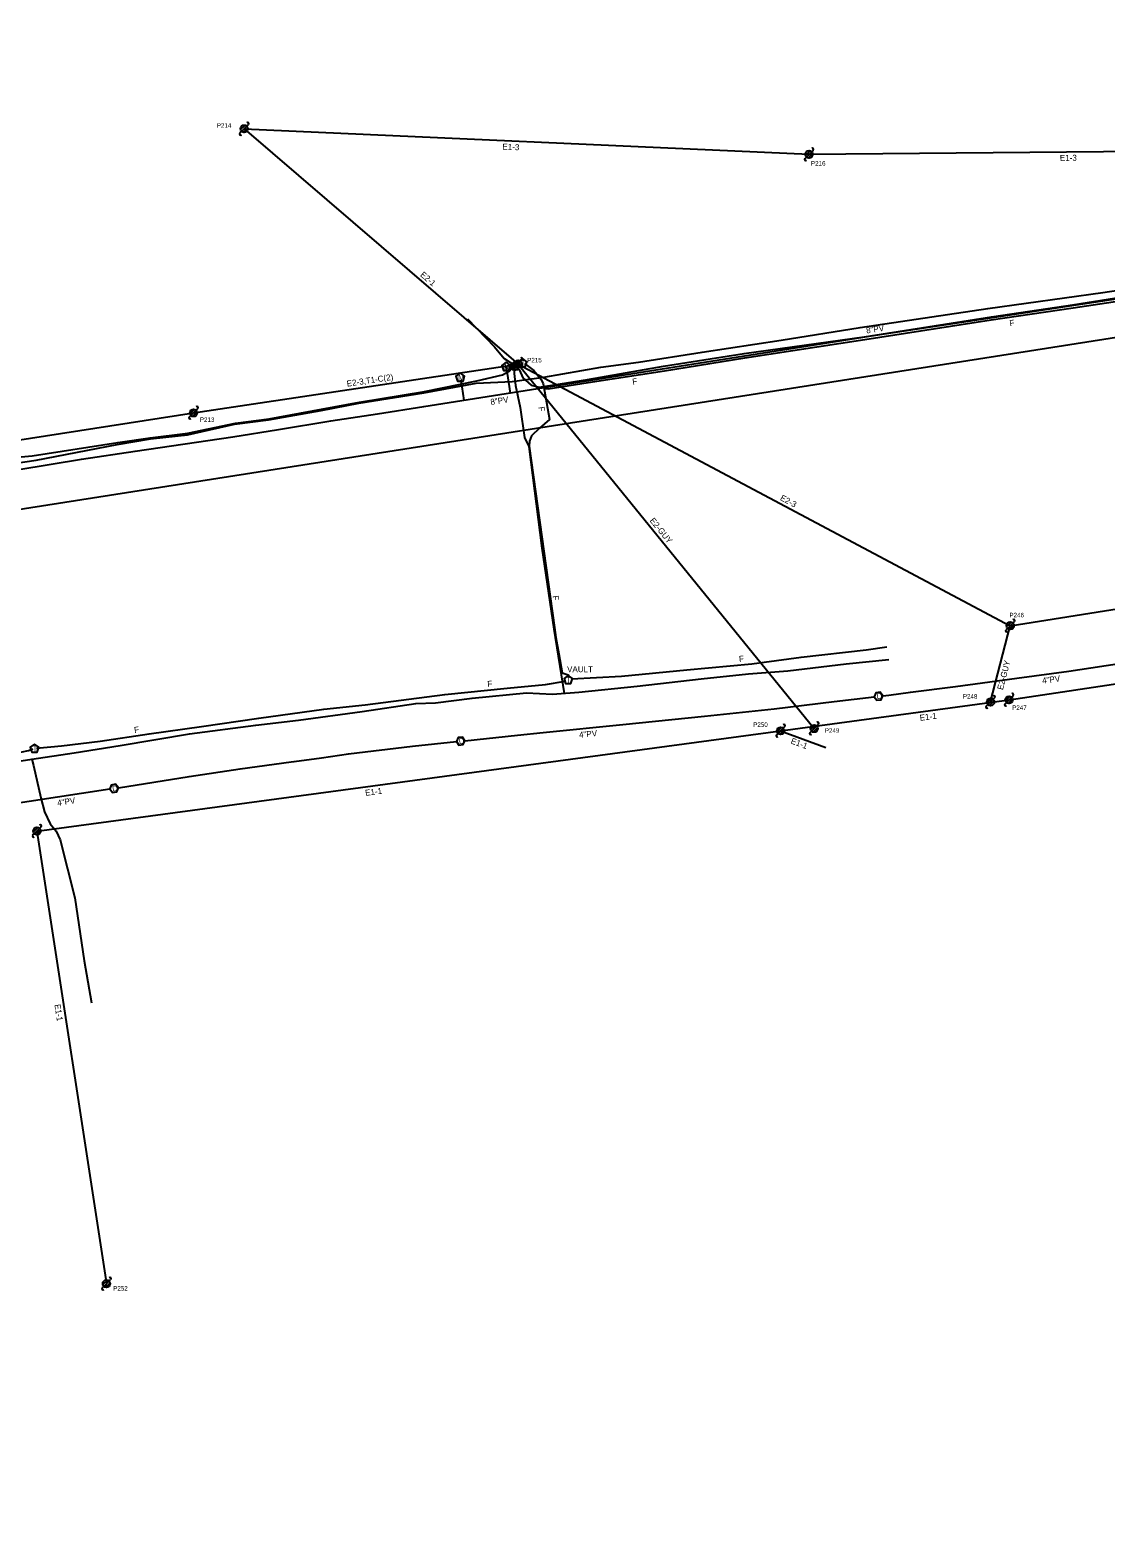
# Model space of a CAD drawing. Extents: x 1614474 to 1865144, y 1098877 to 1212550.
# Drawn here: x 1775065 to 1775781, y 1179234 to 1180237 of the extents above; entities that cross this region are included whole.
import ezdxf

# ---------------------------------------------------------------- set-up
doc = ezdxf.new("R2010")
doc.units = 0
for name, color, linetype in [('BFUSER_FIBERSPAN', 7, 'Continuous'), ('RD_EX_SU_H2O', 7, 'Continuous'), ('RD_EX_SU_Ovhd', 7, 'Continuous'), ('RD_EX_SU_Pole', 7, 'Continuous'), ('RD_EX_SU_Telecom', 7, 'Continuous'), ('RD_EX_SU_TX_H2O', 7, 'Continuous'), ('RD_EX_SU_TX_Pole', 7, 'Continuous'), ('RD_EX_SU_TX_Telecom', 7, 'Continuous')]:
    doc.layers.add(name, color=color, linetype=linetype)

# ---------------------------------------------------------------- blocks, each defined once
blk = doc.blocks.new('SUE_PP')
at = {"layer": 'RD_EX_SU_Pole'}
for p, q in [((-2.4, -0.6), (0.6, 2.4)), ((-1.8, -1.8), (1.8, 1.8)), ((-0.6, -2.4), (2.4, 0.6)), ((1.8, 1.8), (2.8, 2.8)), ((-2.8, -2.8), (-1.8, -1.8))]:
    blk.add_line(p, q, dxfattribs=at)
blk.add_circle((0, 0), 2.5, dxfattribs=at)
for centre, start, end in [((2.3, 3.4), 315, 135), ((-2.3, -3.4), 135, 315)]:
    blk.add_arc(centre, 0.75, start, end, dxfattribs=at)
blk = doc.blocks.new('SUE_TPP')
at = {"layer": 'RD_EX_SU_Telecom'}
blk.add_lwpolyline([(0, 3), (-2.9, 0.9), (-1.8, -2.4), (1.8, -2.4), (2.9, 0.9)], close=True, dxfattribs=at)
blk.add_text('T', height=3.75, dxfattribs=at).set_placement((-1.3, -1.9))
blk = doc.blocks.new('SUE_WM')
at = {"layer": 'RD_EX_SU_H2O'}
blk.add_lwpolyline([(0, 3.1), (-2.9, 0.9), (-1.8, -2.5), (1.8, -2.5), (2.9, 0.9)], close=True, dxfattribs=at)
blk.add_text('M', height=3.75, dxfattribs=at).set_placement((-1.4, -1.9))

msp = doc.modelspace()

# ---------------------------------------------------------------- linework, layer by layer
at = {"layer": 'BFUSER_FIBERSPAN'}
msp.add_lwpolyline([(1772266.1, 1179233.7), (1772993.3, 1179552.4), (1773074.8, 1179562.2), (1773346.2, 1179631.6), (1773610.7, 1179692.1), (1774668.7, 1179856.8), (1776115.7, 1180083.9)], dxfattribs=at)
at = {"layer": 'RD_EX_SU_H2O'}
for p, q in [((1775381.9, 1180012.8), (1775384.6, 1179995.3)), ((1775351.7, 1180003.9), (1775353.8, 1179990.5))]:
    msp.add_line(p, q, dxfattribs=at)
for points in [[(1775079.3, 1179947.9), (1775099.6, 1179951.3), (1775135.1, 1179956.7), (1775200.1, 1179966.2), (1775230.5, 1179971.1), (1775265.3, 1179976.8), (1775296.4, 1179981.4), (1775327.1, 1179986.3), (1775627.5, 1180033.7), (1775910.5, 1180076.5), (1776287.1, 1180136.1), (1776361.3, 1180146.7), (1776578.8, 1180172.8), (1776784.6, 1180199.9), (1777026.8, 1180236.7)], [(1774386.6, 1179840.7), (1774523.7, 1179861.6), (1774695.3, 1179888.5), (1774728, 1179893.4), (1774787.8, 1179902.9), (1774821.8, 1179908.7), (1774868.7, 1179916), (1774901.1, 1179921), (1774935.6, 1179926), (1774973, 1179931.3), (1775005.5, 1179936.4), (1775033.5, 1179940.5), (1775079.3, 1179947.9)], [(1775632.4, 1179793.9), (1775636.3, 1179794.4), (1775650.8, 1179796.3), (1775680.6, 1179800.1), (1775721.5, 1179805.6), (1775756.1, 1179810.3), (1775795.6, 1179816.3), (1775846, 1179823.9)], [(1775354.5, 1179764), (1775389.5, 1179767.7), (1775406.4, 1179769.5), (1775459.4, 1179774.8), (1775513.9, 1179780.3), (1775560.1, 1179785.3), (1775600, 1179790), (1775626.6, 1179793.2)], [(1775124, 1179732.7), (1775171.2, 1179740.1), (1775205.1, 1179745.2), (1775239, 1179749.9), (1775241, 1179750.2), (1775259.1, 1179752.7), (1775277.1, 1179755.2), (1775319.6, 1179760.3), (1775348.8, 1179763.4)], [(1774863.9, 1179692.3), (1774894.8, 1179697.6), (1774947.5, 1179706.1), (1774977.8, 1179710.7), (1775010.9, 1179715.6), (1775118.3, 1179731.9)], [(1775124, 1179732.7), (1775124, 1179732.7)]]:
    msp.add_lwpolyline(points, dxfattribs=at)
for points in [[(1775632.4, 1179793.9), (1775630.6, 1179796.2), (1775627.8, 1179795.9), (1775626.6, 1179793.2), (1775628.4, 1179790.9), (1775631.2, 1179791.3)], [(1775354.5, 1179764), (1775352.8, 1179766.4), (1775350, 1179766.1), (1775348.8, 1179763.4), (1775350.5, 1179761.1), (1775353.4, 1179761.4)], [(1775124, 1179732.7), (1775122.2, 1179735), (1775119.3, 1179734.5), (1775118.3, 1179731.9), (1775120.1, 1179729.6), (1775122.9, 1179730)]]:
    msp.add_lwpolyline(points, close=True, dxfattribs=at)
at = {"layer": 'RD_EX_SU_Ovhd'}
for p, q in [((1775207.7, 1180171.1), (1775389.8, 1180014.6)), ((1775207.7, 1180171.1), (1775583.3, 1180154.1)), ((1775583.3, 1180154.1), (1775904.1, 1180157.1)), ((1775174, 1179982.1), (1775389.8, 1180014.6)), ((1775389.8, 1180014.6), (1775717.1, 1179840.5)), ((1775389.8, 1180014.6), (1775586.7, 1179772.1)), ((1774915.7, 1179942), (1775174, 1179982.1)), ((1775717.1, 1179840.5), (1775883.7, 1179867)), ((1775704, 1179789.8), (1775717.1, 1179840.5)), ((1775716.3, 1179791.2), (1775985, 1179831.9)), ((1775564.4, 1179770.6), (1775716.3, 1179791.2)), ((1775069.9, 1179703.9), (1775564.4, 1179770.6)), ((1775564.4, 1179770.6), (1775594.5, 1179759.4)), ((1775069.9, 1179703.9), (1775116.1, 1179402.8))]:
    msp.add_line(p, q, dxfattribs=at)
at = {"layer": 'RD_EX_SU_Pole'}
for p, q in [((1775585.1, 1180155.8), (1775586.2, 1180156.9)), ((1775580.5, 1180151.2), (1775581.6, 1180152.3)), ((1775580.9, 1180153.4), (1775584, 1180156.5)), ((1775581.6, 1180152.3), (1775585.1, 1180155.8)), ((1775582.7, 1180151.6), (1775585.7, 1180154.7)), ((1775387.4, 1180013.9), (1775390.4, 1180017)), ((1775388, 1180012.8), (1775391.5, 1180016.4)), ((1775391.5, 1180016.4), (1775392.6, 1180017.4)), ((1775387, 1180011.8), (1775388, 1180012.8)), ((1775389.1, 1180012.2), (1775392.2, 1180015.2)), ((1775171.1, 1179979.3), (1775172.2, 1179980.4)), ((1775171.6, 1179981.5), (1775174.6, 1179984.6)), ((1775172.2, 1179980.4), (1775175.7, 1179983.9)), ((1775173.3, 1179979.7), (1775176.4, 1179982.8)), ((1775175.7, 1179983.9), (1775176.8, 1179985)), ((1775714.3, 1179837.7), (1775715.4, 1179838.7)), ((1775714.7, 1179839.9), (1775717.8, 1179842.9)), ((1775715.4, 1179838.7), (1775718.9, 1179842.3)), ((1775716.5, 1179838.1), (1775719.5, 1179841.1)), ((1775718.9, 1179842.3), (1775720, 1179843.3)), ((1775701.2, 1179787), (1775702.2, 1179788.1)), ((1775701.6, 1179789.2), (1775704.6, 1179792.3)), ((1775702.2, 1179788.1), (1775705.7, 1179791.6)), ((1775703.3, 1179787.4), (1775706.4, 1179790.5)), ((1775705.7, 1179791.6), (1775706.8, 1179792.7)), ((1775713.5, 1179788.4), (1775714.6, 1179789.5)), ((1775713.9, 1179790.6), (1775717, 1179793.7)), ((1775714.6, 1179789.5), (1775718.1, 1179793)), ((1775715.7, 1179788.8), (1775718.8, 1179791.9)), ((1775718.1, 1179793), (1775719.2, 1179794.1)), ((1775561.6, 1179767.8), (1775562.7, 1179768.9)), ((1775562, 1179770), (1775565.1, 1179773)), ((1775562.7, 1179768.9), (1775566.2, 1179772.4)), ((1775563.8, 1179768.2), (1775566.9, 1179771.3)), ((1775566.2, 1179772.4), (1775567.3, 1179773.5)), ((1775583.9, 1179769.3), (1775585, 1179770.4)), ((1775584.3, 1179771.5), (1775587.4, 1179774.5)), ((1775585, 1179770.4), (1775588.5, 1179773.9)), ((1775586.1, 1179769.7), (1775589.1, 1179772.8)), ((1775588.5, 1179773.9), (1775589.6, 1179775)), ((1775067.5, 1179703.3), (1775070.5, 1179706.3)), ((1775068.1, 1179702.1), (1775071.6, 1179705.7)), ((1775071.6, 1179705.7), (1775072.7, 1179706.7)), ((1775067, 1179701.1), (1775068.1, 1179702.1)), ((1775069.2, 1179701.5), (1775072.3, 1179704.6))]:
    msp.add_line(p, q, dxfattribs=at)
for centre in [(1775583.3, 1180154.1), (1775389.8, 1180014.6), (1775174, 1179982.1), (1775717.1, 1179840.5), (1775704, 1179789.8), (1775716.3, 1179791.2), (1775564.4, 1179770.6), (1775586.7, 1179772.1), (1775069.9, 1179703.9)]:
    msp.add_circle(centre, 2.5, dxfattribs=at)
for centre, start, end in [((1775585.6, 1180157.4), 315, 135), ((1775581, 1180150.7), 135, 315), ((1775392.1, 1180018), 315, 135), ((1775387.5, 1180011.2), 135, 315), ((1775176.3, 1179985.5), 315, 135), ((1775171.7, 1179978.8), 135, 315), ((1775714.8, 1179837.1), 135, 315), ((1775719.4, 1179843.9), 315, 135), ((1775701.7, 1179786.5), 135, 315), ((1775706.3, 1179793.2), 315, 135), ((1775714, 1179787.9), 135, 315), ((1775718.6, 1179794.6), 315, 135), ((1775589, 1179775.5), 315, 135), ((1775562.1, 1179767.3), 135, 315), ((1775566.7, 1179774), 315, 135), ((1775584.4, 1179768.8), 135, 315), ((1775072.2, 1179707.3), 315, 135), ((1775067.6, 1179700.5), 135, 315)]:
    msp.add_arc(centre, 0.75, start, end, dxfattribs=at)
at = {"layer": 'RD_EX_SU_Telecom'}
for points in [[(1775037.7, 1179945.9), (1775069.3, 1179950.6), (1775123.2, 1179961.1), (1775145.4, 1179964.9), (1775169.9, 1179967.6), (1775201.2, 1179974.6), (1775223.9, 1179977.5), (1775258.9, 1179983.7), (1775284, 1179988.6), (1775327.2, 1179995.4), (1775361.9, 1180001.9), (1775385.8, 1180002.9), (1775406.9, 1180005.8), (1775444.8, 1180012.4), (1775469.8, 1180015.8), (1775512.2, 1180022.4), (1775564.7, 1180030.5), (1775617.4, 1180039), (1775702.3, 1180051.6), (1775778.6, 1180062.1), (1775845.7, 1180072.1)], [(1775388, 1180012.7), (1775390.8, 1180010.6), (1775392.9, 1180005.4), (1775398.5, 1180000.6), (1775403.9, 1179999.3), (1775436, 1180004.3), (1775486.6, 1180013.1), (1775540.2, 1180021.6), (1775620, 1180032.7), (1775704.6, 1180045.9), (1775758.4, 1180054), (1775815.8, 1180063)], [(1775407.1, 1179998.4), (1775409.8, 1179998), (1775436.5, 1180002.4), (1775487.1, 1180010.1), (1775540.6, 1180018.8), (1775620.3, 1180031), (1775704.5, 1180044), (1775758.9, 1180052), (1775816.5, 1180060.6)], [(1775356.1, 1180044.6), (1775374.1, 1180026), (1775380.6, 1180018.3), (1775387.4, 1180013.8)], [(1774916.4, 1179941), (1774920.4, 1179939.4), (1774950.3, 1179943.9), (1774992, 1179946.4), (1775014.9, 1179949.3), (1775047.5, 1179951.7), (1775066.7, 1179953.5), (1775123.7, 1179962.4), (1775145.1, 1179965.6), (1775170.3, 1179968.6), (1775201.9, 1179975.3), (1775224.4, 1179978.2), (1775259, 1179984.5), (1775284.4, 1179989.3), (1775327.6, 1179996.4), (1775362.3, 1180003.4), (1775379.4, 1180007.4), (1775383.8, 1180009.8), (1775387.1, 1180013.3)], [(1775387.5, 1180012.6), (1775387.2, 1180008.4), (1775388.1, 1180000.4), (1775391.2, 1179985.6), (1775394.1, 1179965.8), (1775396.9, 1179959.8)], [(1775394.1, 1180014.9), (1775400.2, 1180010.2), (1775405.1, 1180004.3), (1775406.4, 1180001.5), (1775407.5, 1179996.6), (1775410.8, 1179977.8), (1775404, 1179971.9), (1775398.8, 1179966.8), (1775397.5, 1179963.3), (1775397.2, 1179959.9), (1775414.1, 1179839.3), (1775415, 1179832.6), (1775417, 1179821.7), (1775419.1, 1179809.2), (1775423.2, 1179807.9), (1775423.8, 1179805.9)], [(1775396.9, 1179959.8), (1775405.6, 1179892.2), (1775413.7, 1179838.3), (1775420.5, 1179795.5)], [(1775425.3, 1179805.1), (1775458.6, 1179806.9), (1775502, 1179811.1), (1775545.3, 1179815.2), (1775578.1, 1179819.6), (1775621.3, 1179824.5), (1775635.1, 1179826.4)], [(1775066.5, 1179751.8), (1775094.7, 1179756), (1775125.3, 1179760.9), (1775171.3, 1179768.5), (1775215.5, 1179774.3), (1775243.7, 1179777.6), (1775286.1, 1179783.5), (1775321.8, 1179788.7), (1775334.9, 1179789.3), (1775359.4, 1179792.4), (1775395.4, 1179795.9), (1775412.7, 1179794.9), (1775430.3, 1179796.2), (1775469.1, 1179800.4), (1775511.6, 1179805.2), (1775543, 1179808.6), (1775569.3, 1179810.4), (1775608, 1179815.1), (1775636.3, 1179818.1)], [(1775069.5, 1179759), (1775086.1, 1179760.6), (1775112, 1179763.6), (1775144.6, 1179768.6), (1775179.4, 1179773.5), (1775217.4, 1179779), (1775260.7, 1179785.1), (1775288.2, 1179787.9), (1775341.2, 1179794.7), (1775382.5, 1179799), (1775408, 1179801.5), (1775421.2, 1179803.6)], [(1774491.4, 1179669.3), (1774493.5, 1179668), (1774512.2, 1179669.4), (1774555.8, 1179675.6), (1774603.4, 1179682.2), (1774648.2, 1179689.7), (1774702.1, 1179698.6), (1774733, 1179702.8), (1774777, 1179710.9), (1774837.9, 1179722.2), (1774863.8, 1179726), (1774901.6, 1179732.2), (1774961.5, 1179741.6), (1775003.6, 1179748.2), (1775055.9, 1179755.8), (1775064.3, 1179757.6), (1775067.1, 1179758.6)], [(1775042.1, 1179747.9), (1775066.5, 1179751.8), (1775067.6, 1179747.6), (1775072.5, 1179726.1), (1775075, 1179716.7), (1775078.6, 1179708.7), (1775082.6, 1179703.8), (1775085.4, 1179698.1), (1775095, 1179659.6), (1775101.2, 1179617.6), (1775106.1, 1179589.7)]]:
    msp.add_lwpolyline(points, dxfattribs=at)
for points in [[(1775392.8, 1180018.2), (1775390, 1180016.1), (1775391, 1180012.8), (1775394.6, 1180012.8), (1775395.7, 1180016.1)], [(1775423.2, 1179807.5), (1775420.4, 1179805.4), (1775421.4, 1179802), (1775425, 1179802), (1775426.1, 1179805.4)], [(1775068.3, 1179761.8), (1775065.4, 1179759.7), (1775066.5, 1179756.4), (1775070, 1179756.4), (1775071.1, 1179759.7)]]:
    msp.add_lwpolyline(points, close=True, dxfattribs=at)

# ---------------------------------------------------------------- block references
at = {"layer": 'RD_EX_SU_H2O'}
for p in [(1775351.4, 1180005.6), (1775381.9, 1180012.8)]:
    msp.add_blockref('SUE_WM', p, dxfattribs=at)
at = {"layer": 'RD_EX_SU_Pole'}
for p in [(1775207.7, 1180171.1), (1775116.1, 1179402.8)]:
    msp.add_blockref('SUE_PP', p, dxfattribs=at)
at = {"layer": 'RD_EX_SU_Telecom'}
msp.add_blockref('SUE_TPP', (1775387.8, 1180013.4), dxfattribs=at)

# ---------------------------------------------------------------- texts
at = {"layer": 'RD_EX_SU_H2O'}
for rotation, p in [(6.9094, (1775628.5, 1179791.6)), (6.0433, (1775350.6, 1179761.7)), (8.6121, (1775120.2, 1179730.2))]:
    msp.add_text('D', height=3.75, rotation=rotation, dxfattribs=at).set_placement(p)
at = {"layer": 'RD_EX_SU_Ovhd'}
for s, rotation, p in [('E1-3', 357.3993, (1775379.3, 1180157.3)), ('E1-3', 0.5501, (1775750.1, 1180149.7)), ('E2-1', 319.3118, (1775324.4, 1180073.4)), ('E2-3,T1-C(2)', 8.5529, (1775276.2, 1179999.5)), ('E2-3', 331.9941, (1775563.7, 1179924.3)), ('E2-GUY', 309.0861, (1775477.1, 1179910.3)), ('E2-GUY', 75.4571, (1775712.2, 1179797.5)), ('E1-1', 7.7281, (1775657.2, 1179777.2)), ('E1-1', 339.5994, (1775570.8, 1179762.3)), ('E1-1', 7.6832, (1775288.4, 1179727.3)), ('E1-1', 278.7276, (1775081.5, 1179588.4))]:
    msp.add_text(s, height=4, rotation=rotation, dxfattribs=at).set_placement(p)
at = {"layer": 'RD_EX_SU_Telecom'}
for p in [(1775391.5, 1180013.3), (1775422, 1179802.6), (1775067, 1179756.9)]:
    msp.add_text('T', height=3.75, dxfattribs=at).set_placement(p)
at = {"layer": 'RD_EX_SU_TX_H2O'}
for s, rotation, p in [('8"PV', 8.5849, (1775621.6, 1180034.9)), ('8"PV', 8.9699, (1775371.8, 1179987.3)), ('4"PV', 7.7087, (1775738.6, 1179801.9)), ('4"PV', 5.7156, (1775430.6, 1179765.9)), ('4"PV', 8.6121, (1775083.7, 1179720.6))]:
    msp.add_text(s, height=4, rotation=rotation, dxfattribs=at).set_placement(p)
at = {"layer": 'RD_EX_SU_TX_Pole'}
for s, p in [('P214', (1775189.5, 1180171.8)), ('P216', (1775584.6, 1180146.6)), ('P215', (1775395.9, 1180015.7)), ('P213', (1775178.2, 1179976.1)), ('P246', (1775716.6, 1179846.1)), ('P248', (1775685.6, 1179792)), ('P247', (1775718.4, 1179784.5)), ('P250', (1775546.2, 1179773.2)), ('P249', (1775593.8, 1179769.3)), ('P252', (1775120.6, 1179398.2))]:
    msp.add_text(s, height=3, dxfattribs=at).set_placement(p)
at = {"layer": 'RD_EX_SU_TX_Telecom'}
for rotation, p in [(8.4453, (1775716.9, 1180039.7)), (8.6738, (1775466.1, 1180000.8)), (280.1528, (1775403.3, 1179985.9)), (277.9681, (1775412.7, 1179860.3)), (5.43, (1775536.9, 1179816.4)), (5.9572, (1775369.6, 1179799.7)), (8.7686, (1775134.8, 1179769.1))]:
    msp.add_text('F', height=4, rotation=rotation, dxfattribs=at).set_placement(p)
msp.add_text('VAULT', height=4, dxfattribs=at).set_placement((1775422.4, 1179809.6))

doc.saveas('drawing.dxf')
